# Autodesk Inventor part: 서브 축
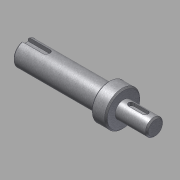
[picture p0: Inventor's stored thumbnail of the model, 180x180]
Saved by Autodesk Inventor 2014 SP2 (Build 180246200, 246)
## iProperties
Created: 2014-10
Part Number: 서브 축
Document SubType Name: Modeling
Designer: KYOUNG IL JANG
Density: 1 g/cm^3
Mass: 19.9624 g
Surface Area: 57.7178 cm^2
Volume: 19.9624 cm^3
Material: 강철, 연강
Appearance: 금속-강(스테인리스, 브러시됨)
Author: SeoGD™ [www.esajin.kr]
Revision Number: 1
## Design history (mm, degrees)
sketch "스케치1"
  geometry: L1 (-16.331, 0)-(-108.831, 0); L2 (-16.331, 0)-(-16.331, -6); L3 (-16.331, -6)-(-38.831, -6); L4 (-38.831, -12.5)-(-46.5, -12.5); L5 (-46.5, -8.5)-(-108.831, -8.5); L6 (-108.831, -8.5)-(-108.831, 0); L7 (-46.5, -8.5)-(-46.5, -12.5); L8 (-38.831, -6)-(-38.831, -12.5); L9 (-46.5, 12.249)-(-46.5, -12.249) reference; L10 (-38.831, -17)-(-38.831, 17) reference; 2 further points
  constraints: 17 end point, 4 perpendicular, 2 collinear, 2 parallel, 1 horizontal, 1 midpoint, 1 point on line
  dimensions: "d1" = 12 diameter of L3 L1; "d2" = 25 diameter of L4 L1; "d3" = 17 diameter of L5 L1; "d18" = 22.5 distance of L2.end L3.end; "d20" = 70 distance between parallel lines of L6 L8; "d21" = 7.66872 distance of L4.start L4.end (derived)
revolve "회전1" sketch "스케치1" stored, may be unused: angle "d5" = 90 deg
chamfer "모따기1" distance "d6" = 1; stored, may be unused: second distance "d7" = 2, angle "d8" = 45 deg
node "작업 평면1"
sketch "스케치2"
  geometry: L1 (11.25, 5)-(11.25, -5) reference; L2 (-5.75, -2)-(4.25, -2); L3 (4.25, 2)-(-5.75, 2); A1 r 2 centre (4.25, 0) between (4.25, -2) and (4.25, 2); A2 r 2 centre (-5.75, 0) between (-5.75, 2) and (-5.75, -2); 2 further points
  constraints: 4 end point, 4 point on circle, 4 tangent, 2 centre point, 1 horizontal alignment, 1 midpoint, 1 parallel, 1 perpendicular
  dimensions: "d9" = 4 distance between parallel lines of L2 L3; "d10" = 14 dimension on A1 A2; "d11" = 5 distance edge to line of A1 L1
extrude "돌출1" cut sketch "스케치2" distance "d12" = 2.5; taper "d13" = 0 deg
node "작업 평면2"
sketch "스케치3"
  geometry: L1 (-31.166, -7.5)-(-31.166, 7.5) reference; L2 (-31.166, 2.5)-(-15.666, 2.5); L3 (-15.666, -2.5)-(-31.166, -2.5); A1 r 2.5 centre (-15.666, 0) between (-15.666, -2.5) and (-15.666, 2.5); 2 further points
  constraints: 4 end point, 2 perpendicular, 2 point on circle, 2 point on line, 2 tangent, 1 centre point, 1 horizontal alignment, 1 midpoint
  dimensions: "d14" = 5 distance between parallel lines of L3 L2; "d15" = 18 dimension on A1 L1
extrude "돌출2" cut sketch "스케치3" distance "d16" = 3; taper "d17" = 0 deg
sketch "스케치4"
  geometry: C1 r 12.5 at (0, 0) reference; 1 further point
extrude "돌출3" join sketch "스케치4" distance "d22" = 3; taper "d23" = 0 deg
chamfer "모따기2" distance "d24" = 1; stored, may be unused: second distance "d25" = 2, angle "d26" = 45 deg
node "솔리드1"
node "참조4"
node "참조5"
